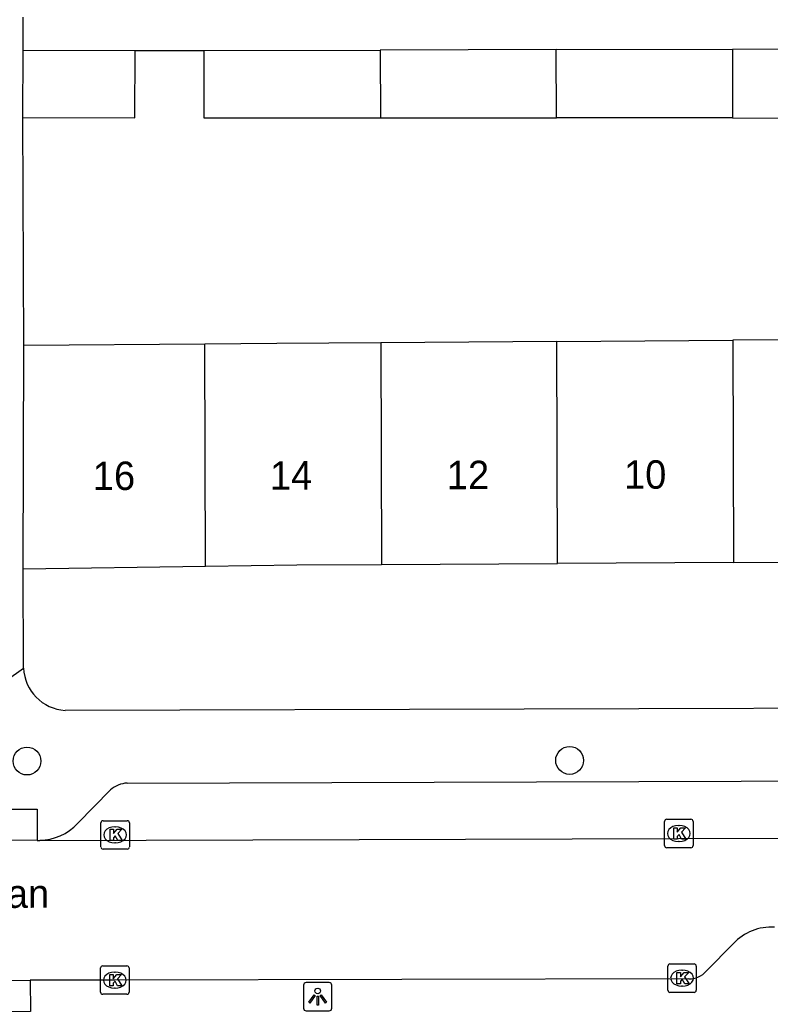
# Model space of a CAD drawing. Extents: x 160732 to 162105, y 387428 to 388479.
# Drawn here: x 161221.14 to 161247.53, y 387806.51 to 387841.43 of the extents above; entities that cross this region are included whole.
import ezdxf

# ---------------------------------------------------------------- set-up
doc = ezdxf.new("R2010")
doc.units = 0
for name, color, linetype in [('IMGEO_Boom', 7, 'Continuous'), ('IMGEO_Kolk', 7, 'Continuous'), ('IMGEO_Lichtpunt', 7, 'Continuous'), ('IMGEO_Openbare_ruimte_label', 7, 'Continuous'), ('IMGEO_Pand', 7, 'Continuous'), ('IMGEO_Pand_nummerreeks', 7, 'Continuous'), ('IMGEO_Rijbaan_lokaal_open', 7, 'Continuous'), ('IMGEO_Voetpad_open', 7, 'Continuous')]:
    doc.layers.add(name, color=color, linetype=linetype)

msp = doc.modelspace()

# ---------------------------------------------------------------- linework, layer by layer
at = {"layer": 'IMGEO_Boom'}
for centre in [(161221.394, 387815.347), (161240.479, 387815.369)]:
    msp.add_circle(centre, 0.489, dxfattribs=at)
at = {"layer": 'IMGEO_Kolk'}
for p, q in [((161223.993, 387812.323), (161223.993, 387813.175)), ((161224.068, 387813.249), (161224.92, 387813.249)), ((161224.994, 387813.175), (161224.994, 387812.323)), ((161243.82, 387812.372), (161243.82, 387813.224)), ((161243.895, 387813.298), (161244.747, 387813.298)), ((161244.821, 387813.224), (161244.821, 387812.372)), ((161224.481, 387813.029), (161224.506, 387813.029)), ((161244.308, 387813.078), (161244.333, 387813.078)), ((161224.504, 387812.469), (161224.479, 387812.469)), ((161244.331, 387812.518), (161244.306, 387812.518)), ((161224.92, 387812.249), (161224.068, 387812.249)), ((161244.747, 387812.298), (161243.895, 387812.298)), ((161223.982, 387807.213), (161223.982, 387808.065)), ((161224.057, 387808.139), (161224.909, 387808.139)), ((161224.47, 387807.919), (161224.495, 387807.919)), ((161224.983, 387808.065), (161224.983, 387807.213)), ((161243.933, 387807.282), (161243.933, 387808.134)), ((161244.008, 387808.208), (161244.86, 387808.208)), ((161244.421, 387807.988), (161244.446, 387807.988)), ((161244.934, 387808.134), (161244.934, 387807.282)), ((161224.493, 387807.359), (161224.468, 387807.359)), ((161244.86, 387807.208), (161244.008, 387807.208)), ((161244.444, 387807.428), (161244.419, 387807.428)), ((161224.909, 387807.139), (161224.057, 387807.139))]:
    msp.add_line(p, q, dxfattribs=at)
for points in [[(161223.993, 387812.323), (161223.993, 387813.175)], [(161224.068, 387813.249), (161224.92, 387813.249)], [(161224.994, 387813.175), (161224.994, 387812.323)], [(161243.82, 387812.372), (161243.82, 387813.224)], [(161243.895, 387813.298), (161244.747, 387813.298)], [(161244.821, 387813.224), (161244.821, 387812.372)], [(161224.314, 387812.949), (161224.437, 387812.949), (161224.437, 387812.798), (161224.567, 387812.949), (161224.731, 387812.949), (161224.585, 387812.798), (161224.738, 387812.549), (161224.586, 387812.549), (161224.501, 387812.713), (161224.437, 387812.646), (161224.437, 387812.549), (161224.314, 387812.549), (161224.314, 387812.949)], [(161244.141, 387812.998), (161244.264, 387812.998), (161244.264, 387812.847), (161244.394, 387812.998), (161244.558, 387812.998), (161244.412, 387812.847), (161244.565, 387812.598), (161244.413, 387812.598), (161244.328, 387812.762), (161244.264, 387812.695), (161244.264, 387812.598), (161244.141, 387812.598), (161244.141, 387812.998)], [(161224.92, 387812.249), (161224.068, 387812.249)], [(161244.747, 387812.298), (161243.895, 387812.298)], [(161223.982, 387807.213), (161223.982, 387808.065)], [(161224.057, 387808.139), (161224.909, 387808.139)], [(161224.983, 387808.065), (161224.983, 387807.213)], [(161243.933, 387807.282), (161243.933, 387808.134)], [(161244.008, 387808.208), (161244.86, 387808.208)], [(161244.254, 387807.908), (161244.377, 387807.908), (161244.377, 387807.757), (161244.507, 387807.908), (161244.671, 387807.908), (161244.525, 387807.757), (161244.678, 387807.508), (161244.526, 387807.508), (161244.441, 387807.672), (161244.377, 387807.605), (161244.377, 387807.508), (161244.254, 387807.508), (161244.254, 387807.908)], [(161244.934, 387808.134), (161244.934, 387807.282)], [(161224.303, 387807.839), (161224.426, 387807.839), (161224.426, 387807.688), (161224.556, 387807.839), (161224.72, 387807.839), (161224.574, 387807.688), (161224.727, 387807.439), (161224.575, 387807.439), (161224.49, 387807.603), (161224.426, 387807.536), (161224.426, 387807.439), (161224.303, 387807.439), (161224.303, 387807.839)], [(161244.86, 387807.208), (161244.008, 387807.208)], [(161224.909, 387807.139), (161224.057, 387807.139)]]:
    msp.add_lwpolyline(points, dxfattribs=at)
for centre, start, end in [((161224.07, 387813.173), 91.552, 178.448), ((161224.07, 387813.173), 91.552, 178.448), ((161224.918, 387813.173), 1.552, 88.448), ((161224.918, 387813.173), 1.552, 88.448), ((161243.897, 387813.222), 91.552, 178.448), ((161243.897, 387813.222), 91.552, 178.448), ((161244.745, 387813.222), 1.552, 88.448), ((161244.745, 387813.222), 1.552, 88.448), ((161224.07, 387812.325), 181.552, 268.448), ((161224.07, 387812.325), 181.552, 268.448), ((161224.918, 387812.325), 271.552, 358.448), ((161224.918, 387812.325), 271.552, 358.448), ((161243.897, 387812.374), 181.552, 268.448), ((161243.897, 387812.374), 181.552, 268.448), ((161244.745, 387812.374), 271.552, 358.448), ((161244.745, 387812.374), 271.552, 358.448), ((161224.059, 387808.063), 91.552, 178.448), ((161224.059, 387808.063), 91.552, 178.448), ((161224.907, 387808.063), 1.552, 88.448), ((161224.907, 387808.063), 1.552, 88.448), ((161244.01, 387808.132), 91.552, 178.448), ((161244.01, 387808.132), 91.552, 178.448), ((161244.858, 387808.132), 1.552, 88.448), ((161244.858, 387808.132), 1.552, 88.448), ((161224.059, 387807.215), 181.552, 268.448), ((161224.059, 387807.215), 181.552, 268.448), ((161224.907, 387807.215), 271.552, 358.448), ((161224.907, 387807.215), 271.552, 358.448), ((161244.01, 387807.284), 181.552, 268.448), ((161244.01, 387807.284), 181.552, 268.448), ((161244.858, 387807.284), 271.552, 358.448), ((161244.858, 387807.284), 271.552, 358.448)]:
    msp.add_arc(centre, 0.0765, start, end, dxfattribs=at)
for centre, major_axis, ratio, start_param, end_param in [((161224.48, 387812.749), (-0.387, 0.002), 0.722429, 4.712389, 7.853982), ((161224.505, 387812.749), (-0.39, 0.002), 0.717154, 1.570796, 4.712389), ((161244.307, 387812.798), (-0.387, 0.002), 0.722429, 4.712389, 7.853982), ((161244.332, 387812.798), (-0.39, 0.002), 0.717154, 1.570796, 4.712389), ((161224.469, 387807.639), (-0.387, 0.002), 0.722429, 4.712389, 7.853982), ((161224.494, 387807.639), (-0.39, 0.002), 0.717154, 1.570796, 4.712389), ((161244.42, 387807.708), (-0.387, 0.002), 0.722429, 4.712389, 7.853982), ((161244.445, 387807.708), (-0.39, 0.002), 0.717154, 1.570796, 4.712389)]:
    msp.add_ellipse(centre, major_axis=major_axis, ratio=ratio, start_param=start_param, end_param=end_param, dxfattribs=at)
at = {"layer": 'IMGEO_Lichtpunt'}
for p, q in [((161231.119, 387807.458), (161231.119, 387806.651)), ((161231.119, 387807.458), (161231.119, 387806.651)), ((161232.021, 387807.553), (161231.213, 387807.553)), ((161232.021, 387807.553), (161231.213, 387807.553)), ((161232.115, 387806.651), (161232.115, 387807.458)), ((161232.115, 387806.651), (161232.115, 387807.458)), ((161231.213, 387806.557), (161232.021, 387806.557)), ((161231.213, 387806.557), (161232.021, 387806.557))]:
    msp.add_line(p, q, dxfattribs=at)
for points in [[(161231.493, 387807.122), (161231.532, 387807.094), (161231.344, 387806.832), (161231.306, 387806.859), (161231.493, 387807.122)], [(161231.595, 387807.074), (161231.642, 387807.074), (161231.642, 387806.752), (161231.595, 387806.752), (161231.595, 387807.074)], [(161231.705, 387807.094), (161231.743, 387807.121), (161231.93, 387806.859), (161231.891, 387806.831), (161231.705, 387807.094)]]:
    msp.add_lwpolyline(points, dxfattribs=at)
msp.add_circle((161231.618, 387807.256), 0.0994, dxfattribs=at)
for centre, start, end in [((161231.213, 387807.458), 90, 180), ((161231.213, 387807.458), 90, 180), ((161232.021, 387807.458), 0, 90), ((161232.021, 387807.458), 0, 90), ((161231.213, 387806.651), 180, 270), ((161231.213, 387806.651), 180, 270), ((161232.021, 387806.651), 270, 0), ((161232.021, 387806.651), 270, 360)]:
    msp.add_arc(centre, 0.0946, start, end, dxfattribs=at)
at = {"layer": 'IMGEO_Pand'}
for points in [[(161240.008, 387840.384), (161233.817, 387840.367)], [(161240.008, 387840.384), (161246.202, 387840.401)], [(161240.014, 387837.98), (161240.008, 387840.384)], [(161246.202, 387840.401), (161250.151, 387840.412)], [(161246.202, 387840.401), (161246.207, 387837.978)], [(161246.207, 387837.978), (161250.15, 387837.976), (161250.151, 387840.412)], [(161221.248, 387837.998), (161221.255, 387840.362)], [(161221.248, 387837.998), (161225.19, 387837.985), (161225.197, 387840.349)], [(161221.255, 387840.362), (161225.197, 387840.349)], [(161227.612, 387840.349), (161233.817, 387840.367)], [(161227.612, 387840.349), (161227.612, 387837.985), (161233.823, 387837.983)], [(161233.817, 387840.367), (161233.823, 387837.983)], [(161233.823, 387837.983), (161240.014, 387837.98)], [(161246.207, 387837.978), (161240.014, 387837.98)], [(161221.256, 387822.117), (161221.281, 387829.974)], [(161227.651, 387830.02), (161221.281, 387829.974)], [(161233.842, 387830.065), (161230.176, 387830.039), (161227.651, 387830.02)], [(161227.67, 387822.204), (161227.651, 387830.02)], [(161240.033, 387830.11), (161233.842, 387830.065)], [(161233.842, 387830.065), (161233.861, 387822.265)], [(161240.033, 387830.11), (161246.225, 387830.155)], [(161240.052, 387822.3), (161240.033, 387830.11)], [(161252.416, 387830.199), (161246.225, 387830.155)], [(161246.225, 387830.155), (161246.243, 387822.336)], [(161227.67, 387822.204), (161230.879, 387822.248), (161233.861, 387822.265)], [(161233.861, 387822.265), (161240.052, 387822.3)], [(161246.243, 387822.336), (161240.052, 387822.3)], [(161246.243, 387822.336), (161252.432, 387822.371)], [(161221.256, 387822.117), (161227.67, 387822.204)]]:
    msp.add_lwpolyline(points, dxfattribs=at)
at = {"layer": 'IMGEO_Rijbaan_lokaal_open'}
for points in [[(161221.753, 387812.557), (161215.604, 387812.56)], [(161221.753, 387812.557), (161221.844, 387812.557)], [(161221.844, 387812.557), (161289.232, 387812.758)], [(161246.245, 387808.922), (161245.284, 387807.957)], [(161214.578, 387807.602), (161221.503, 387807.631)], [(161244.672, 387807.689), (161224.483, 387807.637), (161221.503, 387807.631)]]:
    msp.add_lwpolyline(points, dxfattribs=at)
for centre, radius, start, end in [((161247.56, 387807.722), 1.781, 85.9866, 137.6162), ((161244.717, 387808.42), 0.732, 266.512, 320.786)]:
    msp.add_arc(centre, radius, start, end, dxfattribs=at)
at = {"layer": 'IMGEO_Voetpad_open'}
for points in [[(161221.255, 387840.362), (161221.255, 387841.531)], [(161225.197, 387840.349), (161227.612, 387840.349)], [(161221.281, 387829.974), (161221.248, 387837.998)], [(161221.274, 387818.618), (161221.256, 387822.117)], [(161220.039, 387817.747), (161221.274, 387818.618)], [(161271.169, 387817.264), (161222.736, 387817.131)], [(161224.922, 387814.571), (161286.088, 387814.773)], [(161223.173, 387813.146), (161224.326, 387814.335)], [(161215.604, 387812.56), (161215.608, 387813.655), (161221.75, 387813.653), (161221.753, 387812.557)], [(161221.503, 387807.631), (161221.513, 387806.529), (161214.577, 387806.511), (161214.578, 387807.602)]]:
    msp.add_lwpolyline(points, dxfattribs=at)
for centre, radius, start, end in [((161222.832, 387818.687), 1.559, 182.5488, 266.4797), ((161224.974, 387813.569), 1.004, 92.9787, 130.2258), ((161221.794, 387814.464), 1.907, 271.5013, 316.3036)]:
    msp.add_arc(centre, radius, start, end, dxfattribs=at)

# ---------------------------------------------------------------- texts
at = {"layer": 'IMGEO_Openbare_ruimte_label'}
msp.add_text('Baarle Hertoglaan', height=1, rotation=0.0573, dxfattribs=at).set_placement((161211.397, 387810.172))
at = {"layer": 'IMGEO_Pand_nummerreeks'}
for s, p in [('16', (161223.711, 387824.884)), ('14', (161229.938, 387824.899)), ('12', (161236.162, 387824.914)), ('10', (161242.395, 387824.929))]:
    msp.add_text(s, height=1, rotation=0.1369, dxfattribs=at).set_placement(p)

doc.saveas('drawing.dxf')
